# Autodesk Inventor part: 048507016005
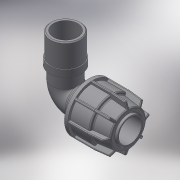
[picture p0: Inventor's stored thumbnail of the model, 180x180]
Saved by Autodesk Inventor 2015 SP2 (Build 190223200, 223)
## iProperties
Created: 2017-08
Part Number: 048507016005
Material: Generic
Description: PLASSON IRRIFIT ELBOW 16-1/2"M
Document SubType Name: Modeling
Designer: KIM
Density: 1 g/cm^3
Appearance: Default
Author: KIM
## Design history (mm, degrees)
derived "048507.ipt"
feature "Solid1::048507.ipt"
tag "TaggingFeature1"
body "Solid1"
other parameters: "d5" = 28.8, "d6" = 12.8, "d10" = 34, "d22" = 22.4, "d24" = 2.4, "d25" = 30.6, "d26" = 27.2, "d31" = 0.8, "d49" = 1.7, "d50" = 0, "d58" = 0.48, "d61" = 360 deg, "d77" = 16, "d78" = 6 deg, "d80" = 17.6, "d81" = 45, "d82" = 2.4, "d84" = 5 deg, "d85" = 70 deg, "d86" = 32.3, "d87" = 0.48, "d88" = 0, "d100" = 27.2, "d101" = 8, "d102" = 0, "d103" = 20.955, "d104" = 22.00275, "d105" = 16, "d107" = 16, "d108" = 18.8595, "d109" = 17.6, "d110" = 16.764, "d111" = 20.8, "d113" = 0.62865, "d120" = 9, "d121" = 9, "d122" = 38, "d123" = 18.8595, "d124" = 2.25, "d125" = 90 deg, "d_" = 16, "E_" = 34, "A_" = 45, "l_" = 16, "A_1" = 38, "l_2" = 16, "R_" = 20.955, "d99" = 22.4
